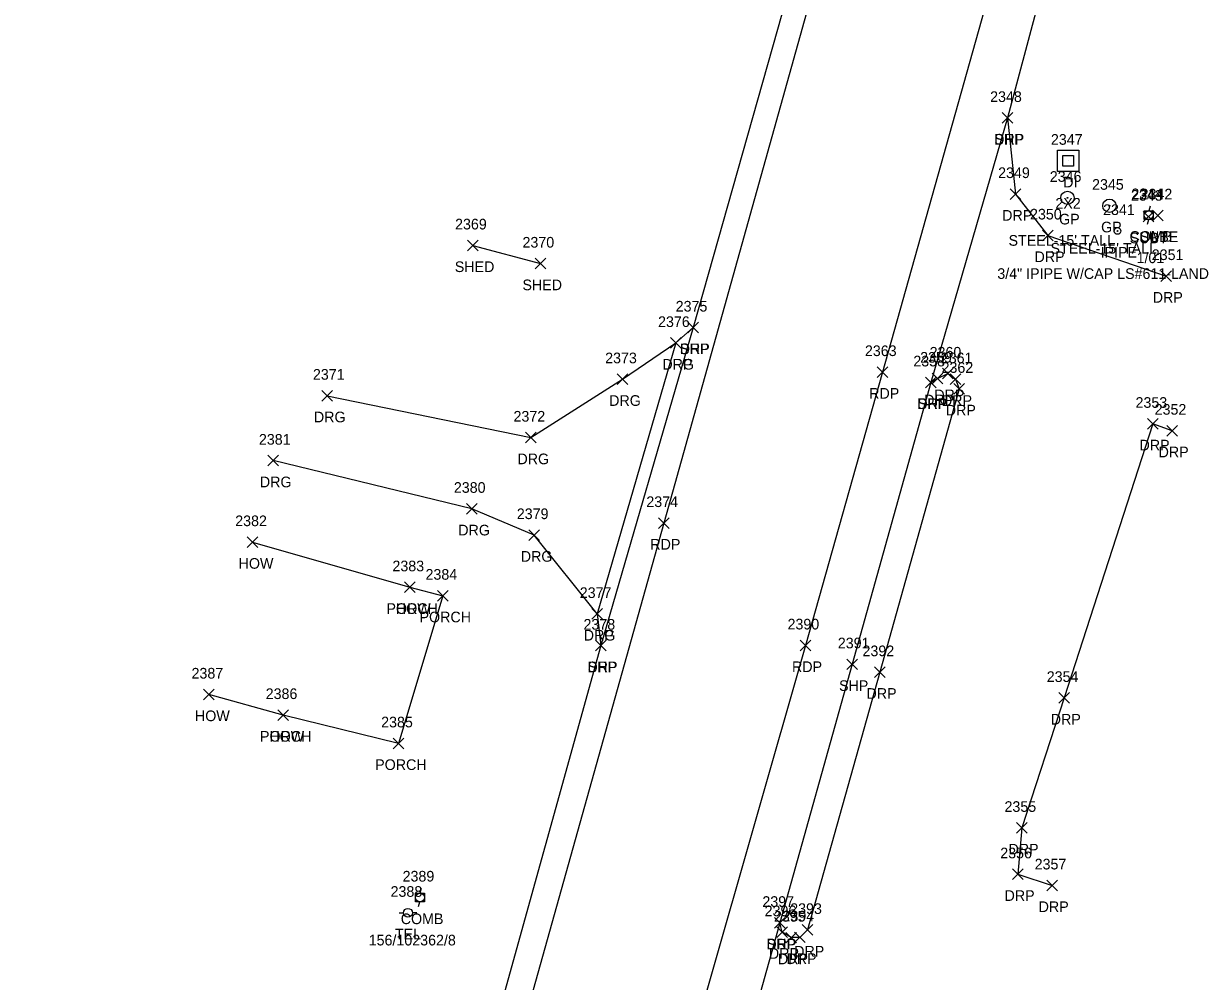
# Model space of a CAD drawing. Extents: x 1443071 to 1445292, y 614024 to 622563.
# Drawn here: x 1444199 to 1444421.4, y 621040.9 to 621220.7 of the extents above; entities that cross this region are included whole.
import ezdxf

# ---------------------------------------------------------------- set-up
doc = ezdxf.new("R2010")
doc.units = 0
for name, color, linetype in [('D_A', 7, 'Continuous'), ('D_C', 7, 'Continuous'), ('D_I', 7, 'Continuous'), ('DS', 7, 'Continuous'), ('L_A', 7, 'Continuous'), ('L_I', 7, 'Continuous'), ('L_TIC', 7, 'Continuous'), ('LBC', 7, 'Continuous'), ('LBF', 7, 'Continuous'), ('M_A', 7, 'Continuous'), ('M_C', 7, 'Continuous'), ('M_I', 7, 'Continuous'), ('MPIP', 7, 'Continuous'), ('P_A', 7, 'Continuous'), ('P_I', 7, 'Continuous'), ('P_TIC', 7, 'Continuous'), ('PET', 7, 'Continuous'), ('PSP', 7, 'Continuous'), ('R_A', 7, 'Continuous'), ('R_C', 7, 'Continuous'), ('R_I', 7, 'Continuous'), ('R_TIC', 7, 'Continuous'), ('RDG', 7, 'Continuous'), ('RDP', 7, 'Continuous'), ('RGP', 7, 'Continuous'), ('U_A', 7, 'Continuous'), ('U_C', 7, 'Continuous'), ('U_I', 7, 'Continuous'), ('U_TIC', 7, 'Continuous'), ('UP', 7, 'Continuous')]:
    doc.layers.add(name, color=color, linetype=linetype)

msp = doc.modelspace()

# ---------------------------------------------------------------- linework, layer by layer
at = {"layer": 'DS'}
for p, q in [((1444393.1, 621197), (1444397.1, 621197)), ((1444393.1, 621193), (1444393.1, 621197)), ((1444394.1, 621194), (1444394.1, 621196)), ((1444394.1, 621196), (1444396.1, 621196)), ((1444396.1, 621196), (1444396.1, 621194)), ((1444397.1, 621197), (1444397.1, 621193)), ((1444397.1, 621193), (1444393.1, 621193)), ((1444396.1, 621194), (1444394.1, 621194)), ((1444395.1, 621195), (1444395.1, 621195)), ((1444395.1, 621195), (1444395.1, 621195))]:
    msp.add_line(p, q, dxfattribs=at)
at = {"layer": 'L_TIC'}
for points in [[(1444282.28, 621178.1), (1444284.28, 621180.1)], [(1444284.28, 621178.1), (1444282.28, 621180.1)], [(1444282.28, 621178.1), (1444284.28, 621180.1)], [(1444284.28, 621178.1), (1444282.28, 621180.1)], [(1444294.98, 621174.69), (1444296.98, 621176.69)], [(1444296.98, 621174.69), (1444294.98, 621176.69)], [(1444240.95, 621122.38), (1444242.95, 621124.38)], [(1444242.95, 621122.38), (1444240.95, 621124.38)], [(1444270.47, 621113.9), (1444272.47, 621115.9)], [(1444272.47, 621113.9), (1444270.47, 621115.9)], [(1444270.47, 621113.9), (1444272.47, 621115.9)], [(1444272.47, 621113.9), (1444270.47, 621115.9)], [(1444276.68, 621112.32), (1444278.68, 621114.32)], [(1444278.68, 621112.32), (1444276.68, 621114.32)], [(1444232.75, 621093.76), (1444234.75, 621095.76)], [(1444234.75, 621093.76), (1444232.75, 621095.76)], [(1444246.72, 621089.91), (1444248.72, 621091.91)], [(1444248.72, 621089.91), (1444246.72, 621091.91)], [(1444246.72, 621089.91), (1444248.72, 621091.91)], [(1444248.72, 621089.91), (1444246.72, 621091.91)], [(1444268.35, 621084.59), (1444270.35, 621086.59)], [(1444270.35, 621084.59), (1444268.35, 621086.59)]]:
    msp.add_lwpolyline(points, dxfattribs=at)
at = {"layer": 'LBC'}
for points in [[(1444283.28, 621179.1), (1444295.98, 621175.69)], [(1444241.95, 621123.38), (1444271.47, 621114.9)], [(1444247.72, 621090.91), (1444233.75, 621094.76)]]:
    msp.add_lwpolyline(points, dxfattribs=at)
at = {"layer": 'LBF'}
msp.add_lwpolyline([(1444271.47, 621114.9), (1444277.68, 621113.32), (1444269.35, 621085.59), (1444247.72, 621090.91)], dxfattribs=at)
at = {"layer": 'MPIP'}
for radius in [0.625, 0.0833]:
    msp.add_circle((1444404.33, 621181.81), radius, dxfattribs=at)
at = {"layer": 'P_TIC'}
for points in [[(1444382.69, 621202.04), (1444384.69, 621204.04)], [(1444384.69, 621202.04), (1444382.69, 621204.04)], [(1444323.65, 621162.68), (1444325.65, 621164.68)], [(1444325.65, 621162.68), (1444323.65, 621164.68)], [(1444359.23, 621154.32), (1444361.23, 621156.32)], [(1444361.23, 621154.32), (1444359.23, 621156.32)], [(1444368.27, 621152.38), (1444370.27, 621154.38)], [(1444370.27, 621152.38), (1444368.27, 621154.38)], [(1444318.14, 621125.97), (1444320.14, 621127.97)], [(1444320.14, 621125.97), (1444318.14, 621127.97)], [(1444306.34, 621102.94), (1444308.34, 621104.94)], [(1444308.34, 621102.94), (1444306.34, 621104.94)], [(1444344.74, 621102.98), (1444346.74, 621104.98)], [(1444346.74, 621102.98), (1444344.74, 621104.98)], [(1444353.52, 621099.43), (1444355.52, 621101.43)], [(1444355.52, 621099.43), (1444353.52, 621101.43)], [(1444339.93, 621050.88), (1444341.93, 621052.88)], [(1444341.93, 621050.88), (1444339.93, 621052.88)]]:
    msp.add_lwpolyline(points, dxfattribs=at)
at = {"layer": 'PET'}
for points in [[(1444393.99, 621275.61), (1444360.23, 621155.32), (1444345.74, 621103.98), (1444299.41, 620941.8), (1444273.27, 620844.52), (1444244.09, 620730.97), (1444221.37, 620651.37), (1444196.75, 620548.06), (1444177.44, 620486.23), (1444161.6, 620423.84), (1444143.45, 620356.38), (1444122.97, 620254.68), (1444105.94, 620160.17), (1444094.56, 620089.52), (1444083.91, 620011.71), (1444077.6, 619958.52), (1444073.05, 619913.75)], [(1444350.41, 621238.76), (1444319.14, 621126.97), (1444291.55, 621028.33), (1444258.02, 620908.98), (1444225.45, 620794.19), (1444210.22, 620737.59), (1444176.75, 620619.09), (1444153.1, 620523.45), (1444139.28, 620467.17), (1444131.97, 620435.45), (1444113.12, 620363.38), (1444103.37, 620315.76), (1444093.47, 620268.1), (1444084.86, 620222.29), (1444073.72, 620159.9), (1444065.08, 620092.83), (1444054.27, 620016.44), (1444048.57, 619960.86), (1444043.42, 619916.17), (1444073.05, 619913.75)]]:
    msp.add_lwpolyline(points, dxfattribs=at)
at = {"layer": 'PSP'}
for points in [[(1444397.04, 621252.99), (1444383.69, 621203.04), (1444369.27, 621153.38), (1444354.52, 621100.43), (1444340.93, 621051.88), (1444329.46, 621010.72), (1444321.22, 620981.83), (1444295.58, 620890.64), (1444282.49, 620842.68), (1444250.85, 620729.5), (1444228.91, 620648.98), (1444202.76, 620547.52)], [(1444345.99, 621239.2), (1444324.65, 621163.68), (1444307.34, 621103.94), (1444286.44, 621028.71), (1444253.5, 620910.47), (1444226.49, 620812.23), (1444217.75, 620781.55), (1444205.71, 620738.94), (1444173.15, 620620.17), (1444162.97, 620582.35)]]:
    msp.add_lwpolyline(points, dxfattribs=at)
at = {"layer": 'R_TIC'}
for points in [[(1444382.69, 621202.04), (1444384.69, 621204.04)], [(1444384.69, 621202.04), (1444382.69, 621204.04)], [(1444384.2, 621187.75), (1444386.2, 621189.75)], [(1444386.2, 621187.75), (1444384.2, 621189.75)], [(1444390.27, 621179.97), (1444392.27, 621181.97)], [(1444392.27, 621179.97), (1444390.27, 621181.97)], [(1444412.47, 621172.35), (1444414.47, 621174.35)], [(1444414.47, 621172.35), (1444412.47, 621174.35)], [(1444323.65, 621162.68), (1444325.65, 621164.68)], [(1444325.65, 621162.68), (1444323.65, 621164.68)], [(1444320.4, 621159.78), (1444322.4, 621161.78)], [(1444322.4, 621159.78), (1444320.4, 621161.78)], [(1444320.4, 621159.78), (1444322.4, 621161.78)], [(1444322.4, 621159.78), (1444320.4, 621161.78)], [(1444369.56, 621153.08), (1444371.56, 621155.08)], [(1444371.56, 621153.08), (1444369.56, 621155.08)], [(1444371.46, 621154.03), (1444373.46, 621156.03)], [(1444373.46, 621154.03), (1444371.46, 621156.03)], [(1444372.91, 621152.97), (1444374.91, 621154.97)], [(1444374.91, 621152.97), (1444372.91, 621154.97)], [(1444310.41, 621152.97), (1444312.41, 621154.97)], [(1444312.41, 621152.97), (1444310.41, 621154.97)], [(1444368.27, 621152.38), (1444370.27, 621154.38)], [(1444370.27, 621152.38), (1444368.27, 621154.38)], [(1444373.61, 621151.17), (1444375.61, 621153.17)], [(1444375.61, 621151.17), (1444373.61, 621153.17)], [(1444254.98, 621149.88), (1444256.98, 621151.88)], [(1444256.98, 621149.88), (1444254.98, 621151.88)], [(1444409.99, 621144.6), (1444411.99, 621146.6)], [(1444411.99, 621144.6), (1444409.99, 621146.6)], [(1444293.2, 621142.01), (1444295.2, 621144.01)], [(1444295.2, 621142.01), (1444293.2, 621144.01)], [(1444413.58, 621143.31), (1444415.58, 621145.31)], [(1444415.58, 621143.31), (1444413.58, 621145.31)], [(1444244.83, 621137.68), (1444246.83, 621139.68)], [(1444246.83, 621137.68), (1444244.83, 621139.68)], [(1444282.09, 621128.64), (1444284.09, 621130.64)], [(1444284.09, 621128.64), (1444282.09, 621130.64)], [(1444293.82, 621123.7), (1444295.82, 621125.7)], [(1444295.82, 621123.7), (1444293.82, 621125.7)], [(1444305.64, 621108.89), (1444307.64, 621110.89)], [(1444307.64, 621108.89), (1444305.64, 621110.89)], [(1444305.64, 621108.89), (1444307.64, 621110.89)], [(1444307.64, 621108.89), (1444305.64, 621110.89)], [(1444306.34, 621102.94), (1444308.34, 621104.94)], [(1444308.34, 621102.94), (1444306.34, 621104.94)], [(1444358.73, 621097.96), (1444360.73, 621099.96)], [(1444360.73, 621097.96), (1444358.73, 621099.96)], [(1444393.32, 621093.12), (1444395.32, 621095.12)], [(1444395.32, 621093.12), (1444393.32, 621095.12)], [(1444385.39, 621068.72), (1444387.39, 621070.72)], [(1444387.39, 621068.72), (1444385.39, 621070.72)], [(1444384.65, 621060), (1444386.65, 621062)], [(1444386.65, 621060), (1444384.65, 621062)], [(1444391.05, 621057.91), (1444393.05, 621059.91)], [(1444393.05, 621057.91), (1444391.05, 621059.91)], [(1444339.93, 621050.88), (1444341.93, 621052.88)], [(1444341.93, 621050.88), (1444339.93, 621052.88)], [(1444340.41, 621049.13), (1444342.41, 621051.13)], [(1444342.41, 621049.13), (1444340.41, 621051.13)], [(1444345.15, 621049.55), (1444347.15, 621051.55)], [(1444347.15, 621049.55), (1444345.15, 621051.55)], [(1444342.1, 621048.1), (1444344.1, 621050.1)], [(1444344.1, 621048.1), (1444342.1, 621050.1)], [(1444343.71, 621048.16), (1444345.71, 621050.16)], [(1444345.71, 621048.16), (1444343.71, 621050.16)]]:
    msp.add_lwpolyline(points, dxfattribs=at)
at = {"layer": 'RDG'}
for points in [[(1444255.98, 621150.88), (1444294.2, 621143.01), (1444311.41, 621153.97), (1444321.4, 621160.78)], [(1444306.64, 621109.89), (1444294.82, 621124.7), (1444283.09, 621129.64), (1444245.83, 621138.68)]]:
    msp.add_lwpolyline(points, dxfattribs=at)
at = {"layer": 'RDP'}
for points in [[(1444383.69, 621203.04), (1444385.2, 621188.75), (1444391.27, 621180.97), (1444413.47, 621173.35)], [(1444324.65, 621163.68), (1444321.4, 621160.78), (1444306.64, 621109.89), (1444307.34, 621103.94)], [(1444369.27, 621153.38), (1444370.56, 621154.08), (1444372.46, 621155.03), (1444373.91, 621153.97), (1444374.61, 621152.17), (1444359.73, 621098.96), (1444346.15, 621050.55), (1444344.71, 621049.16), (1444343.1, 621049.1), (1444341.41, 621050.13), (1444340.93, 621051.88)], [(1444414.58, 621144.31), (1444410.99, 621145.6), (1444394.32, 621094.12), (1444386.39, 621069.72), (1444385.65, 621061), (1444392.05, 621058.91)]]:
    msp.add_lwpolyline(points, dxfattribs=at)
at = {"layer": 'RGP'}
for p, q in [((1444394.94, 621188.04), (1444394.94, 621188.04)), ((1444402.83, 621186.55), (1444402.83, 621186.55))]:
    msp.add_line(p, q, dxfattribs=at)
for centre, radius in [((1444394.94, 621188.04), 1.25), ((1444394.94, 621188.04), 0.0833), ((1444402.83, 621186.55), 1.25), ((1444402.83, 621186.55), 0.0833)]:
    msp.add_circle(centre, radius, dxfattribs=at)
at = {"layer": 'U_TIC'}
for points in [[(1444409.14, 621183.5), (1444411.14, 621185.5)], [(1444411.14, 621183.5), (1444409.14, 621185.5)], [(1444410.94, 621183.73), (1444412.94, 621185.73)], [(1444412.94, 621183.73), (1444410.94, 621185.73)]]:
    msp.add_lwpolyline(points, dxfattribs=at)
at = {"layer": 'UP'}
for p, q in [((1444410.46, 621186.45), (1444410.21, 621185.62)), ((1444409.38, 621183.95), (1444409.38, 621185.62)), ((1444409.38, 621185.62), (1444411.04, 621185.62)), ((1444411.04, 621183.95), (1444409.38, 621183.95)), ((1444409.96, 621183.12), (1444410.21, 621183.95)), ((1444410.21, 621184.78), (1444410.21, 621184.78)), ((1444411.04, 621185.62), (1444411.04, 621183.95)), ((1444272.55, 621055.81), (1444272.55, 621057.47)), ((1444272.55, 621057.47), (1444274.22, 621057.47)), ((1444273.63, 621058.31), (1444273.38, 621057.47)), ((1444274.22, 621057.47), (1444274.22, 621055.81)), ((1444274.22, 621055.81), (1444272.55, 621055.81)), ((1444273.13, 621054.97), (1444273.38, 621055.81)), ((1444273.38, 621056.64), (1444273.38, 621056.64)), ((1444269.46, 621053.77), (1444270.28, 621053.77)), ((1444271.12, 621053.77), (1444271.12, 621053.77)), ((1444272.78, 621053.77), (1444271.95, 621053.77)), ((1444271.95, 621053.77), (1444271.95, 621053.77)), ((1444272.78, 621053.77), (1444272.78, 621053.77))]:
    msp.add_line(p, q, dxfattribs=at)
for centre in [(1444410.21, 621184.78), (1444273.38, 621056.64), (1444271.12, 621053.77)]:
    msp.add_circle(centre, 0.833, dxfattribs=at)

# ---------------------------------------------------------------- texts
at = {"layer": 'D_A'}
msp.add_text('DI', height=2, dxfattribs=at).set_placement((1444394.16, 621190))
at = {"layer": 'D_C'}
msp.add_text('2X2', height=2, dxfattribs=at).set_placement((1444392.68, 621186))
at = {"layer": 'D_I'}
msp.add_text('2347', height=2, dxfattribs=at).set_placement((1444391.84, 621198))
at = {"layer": 'L_A'}
for s, p in [('SHED', (1444279.92, 621174.1)), ('SHED', (1444279.92, 621174.1)), ('SHED', (1444292.62, 621170.69)), ('HOW', (1444239.33, 621118.38)), ('PORCH', (1444267.09, 621109.9)), ('HOW', (1444268.86, 621109.9)), ('PORCH', (1444273.3, 621108.32)), ('HOW', (1444231.13, 621089.76)), ('PORCH', (1444243.34, 621085.91)), ('HOW', (1444245.11, 621085.91)), ('PORCH', (1444264.97, 621080.59))]:
    msp.add_text(s, height=2, dxfattribs=at).set_placement(p)
at = {"layer": 'L_I'}
for s, p in [('2369', (1444279.97, 621182.1)), ('2369', (1444279.97, 621182.1)), ('2370', (1444292.63, 621178.69)), ('2382', (1444238.69, 621126.38)), ('2383', (1444268.21, 621117.9)), ('2383', (1444268.21, 621117.9)), ('2384', (1444274.42, 621116.32)), ('2387', (1444230.49, 621097.76)), ('2386', (1444244.41, 621093.91)), ('2386', (1444244.41, 621093.91)), ('2385', (1444266.09, 621088.59))]:
    msp.add_text(s, height=2, dxfattribs=at).set_placement(p)
at = {"layer": 'M_A'}
msp.add_text('IPIPE', height=2, dxfattribs=at).set_placement((1444401.17, 621176.81))
at = {"layer": 'M_C'}
msp.add_text('3/4" IPIPE W/CAP LS#611-LAND', height=2, dxfattribs=at).set_placement((1444381.78, 621172.81))
at = {"layer": 'M_I'}
msp.add_text('2341', height=2, dxfattribs=at).set_placement((1444401.64, 621184.81))
at = {"layer": 'P_A'}
for s, p in [('SHP', (1444381.23, 621198.04)), ('SHP', (1444322.19, 621158.68)), ('RDP', (1444357.72, 621150.32)), ('SHP', (1444366.81, 621148.38)), ('RDP', (1444316.63, 621121.97)), ('SHP', (1444304.87, 621098.94)), ('RDP', (1444343.23, 621098.98)), ('SHP', (1444352.06, 621095.43)), ('SHP', (1444338.47, 621046.88))]:
    msp.add_text(s, height=2, dxfattribs=at).set_placement(p)
at = {"layer": 'P_I'}
for s, p in [('2348', (1444380.43, 621206.04)), ('2375', (1444321.39, 621166.68)), ('2363', (1444356.92, 621158.32)), ('2358', (1444366.01, 621156.38)), ('2374', (1444315.88, 621129.97)), ('2378', (1444304.08, 621106.94)), ('2390', (1444342.39, 621106.98)), ('2391', (1444351.83, 621103.43)), ('2397', (1444337.67, 621054.88))]:
    msp.add_text(s, height=2, dxfattribs=at).set_placement(p)
at = {"layer": 'R_A'}
for s, p in [('DRP', (1444381.18, 621198.04)), ('DRP', (1444382.69, 621183.75)), ('GP', (1444393.38, 621183.04)), ('GP', (1444401.26, 621181.55)), ('DRP', (1444388.76, 621175.97)), ('DRP', (1444410.96, 621168.35)), ('DRP', (1444322.14, 621158.68)), ('DRG', (1444318.89, 621155.78)), ('DRP', (1444318.89, 621155.78)), ('DRG', (1444308.9, 621148.97)), ('DRP', (1444368.04, 621149.08)), ('DRP', (1444369.95, 621150.03)), ('DRP', (1444371.39, 621148.97)), ('DRP', (1444366.76, 621148.38)), ('DRP', (1444372.1, 621147.17)), ('DRG', (1444253.47, 621145.88)), ('DRP', (1444408.48, 621140.6)), ('DRG', (1444291.68, 621138.01)), ('DRP', (1444412.06, 621139.31)), ('DRG', (1444243.32, 621133.68)), ('DRG', (1444280.57, 621124.64)), ('DRG', (1444292.31, 621119.7)), ('DRG', (1444304.13, 621104.89)), ('DRP', (1444304.13, 621104.89)), ('DRP', (1444304.82, 621098.94)), ('DRP', (1444357.22, 621093.96)), ('DRP', (1444391.81, 621089.12)), ('DRP', (1444383.88, 621064.72)), ('DRP', (1444383.14, 621056)), ('DRP', (1444389.54, 621053.91)), ('DRP', (1444338.42, 621046.88)), ('DRP', (1444338.89, 621045.13)), ('DRP', (1444340.59, 621044.1)), ('DRP', (1444342.19, 621044.16)), ('DRP', (1444343.64, 621045.55))]:
    msp.add_text(s, height=2, dxfattribs=at).set_placement(p)
at = {"layer": 'R_C'}
for p in [(1444383.89, 621179.04), (1444391.77, 621177.55)]:
    msp.add_text("STEEL-15' TALL", height=2, dxfattribs=at).set_placement(p)
at = {"layer": 'R_I'}
for s, p in [('2348', (1444380.43, 621206.04)), ('2349', (1444381.93, 621191.75)), ('2346', (1444391.63, 621191.04)), ('2345', (1444399.57, 621189.55)), ('2350', (1444387.92, 621183.97)), ('2351', (1444410.78, 621176.35)), ('2375', (1444321.39, 621166.68)), ('2376', (1444318.08, 621163.78)), ('2376', (1444318.08, 621163.78)), ('2360', (1444369.07, 621158.03)), ('2373', (1444308.15, 621156.97)), ('2358', (1444366.01, 621156.38)), ('2359', (1444367.29, 621157.08)), ('2361', (1444371.17, 621156.97)), ('2362', (1444371.31, 621155.17)), ('2371', (1444253.28, 621153.88)), ('2353', (1444407.73, 621148.6)), ('2352', (1444411.32, 621147.31)), ('2372', (1444290.94, 621146.01)), ('2381', (1444243.14, 621141.68)), ('2380', (1444279.74, 621132.64)), ('2379', (1444291.56, 621127.7)), ('2377', (1444303.38, 621112.89)), ('2377', (1444303.38, 621112.89)), ('2378', (1444304.08, 621106.94)), ('2392', (1444356.47, 621101.96)), ('2354', (1444391.06, 621097.12)), ('2355', (1444383.13, 621072.72)), ('2356', (1444382.33, 621064)), ('2357', (1444388.79, 621061.91)), ('2397', (1444337.67, 621054.88)), ('2396', (1444338.09, 621053.13)), ('2393', (1444342.89, 621053.55)), ('2395', (1444339.84, 621052.1)), ('2394', (1444341.45, 621052.16))]:
    msp.add_text(s, height=2, dxfattribs=at).set_placement(p)
at = {"layer": 'U_A'}
for s, p in [('COMB', (1444406.6, 621179.78)), ('SUBE', (1444408.47, 621179.73)), ('SUBT', (1444406.63, 621179.5)), ('COMB', (1444269.77, 621051.64)), ('TEL', (1444268.68, 621048.77))]:
    msp.add_text(s, height=2, dxfattribs=at).set_placement(p)
at = {"layer": 'U_C'}
for s, p in [('1/01', (1444407.93, 621175.78)), ('156/102362/8', (1444263.75, 621047.64))]:
    msp.add_text(s, height=2, dxfattribs=at).set_placement(p)
at = {"layer": 'U_I'}
for s, p in [('2343', (1444406.88, 621187.5)), ('2344', (1444406.95, 621187.78)), ('2342', (1444408.68, 621187.73)), ('2389', (1444270.12, 621059.64)), ('2388', (1444267.86, 621056.77))]:
    msp.add_text(s, height=2, dxfattribs=at).set_placement(p)

doc.saveas('drawing.dxf')
